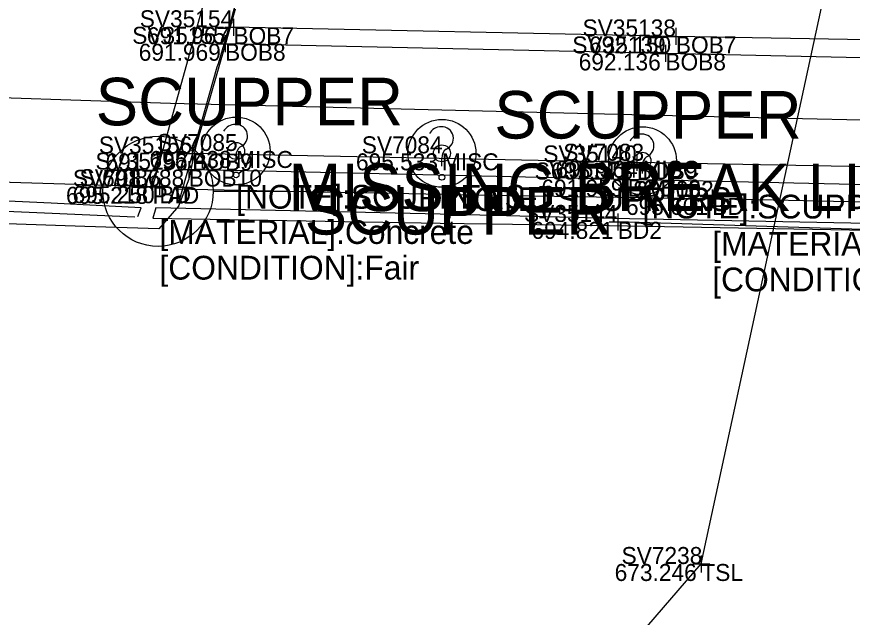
# Model space of a CAD drawing. Extents: x 1659932 to 1663108, y 619867 to 620611.
# Drawn here: x 1661219.34 to 1661268.55, y 620192.48 to 620227.86 of the extents above; entities that cross this region are included whole.
import ezdxf

# ---------------------------------------------------------------- set-up
doc = ezdxf.new("R2010")
doc.units = 0
for name, color, linetype in [('BR_X_Rail_Object', 7, 'Continuous'), ('BR_X_SV_Abut', 7, 'Continuous'), ('BR_X_SV_Bottom_of_Beam', 7, 'Continuous'), ('BR_X_SV_Bottom_of_Beam_Text', 7, 'Continuous'), ('BR_X_SV_Deck_Top', 7, 'Continuous'), ('BR_X_SV_Deck_Top_Text', 7, 'Continuous'), ('PM_X_Edge_Line', 7, 'Continuous'), ('RD_X_Concrete_Pad', 7, 'Continuous'), ('RD_X_Misc_Items', 7, 'Continuous'), ('RD_X_Text', 7, 'Continuous'), ('SC_Scratch6', 7, 'Continuous'), ('SV_X_Break_Lines', 7, 'Continuous'), ('SV_X_Shot_Marker', 7, 'Continuous'), ('SV_X_Text', 7, 'Continuous'), ('SV_X_Text_Comment', 7, 'Continuous'), ('SV_X_Text_Elevation', 7, 'Continuous'), ('SV_X_Text_Name', 7, 'Continuous'), ('SV_X_Toe_of_Slope', 7, 'Continuous')]:
    doc.layers.add(name, color=color, linetype=linetype)

msp = doc.modelspace()

# ---------------------------------------------------------------- linework, layer by layer
at = {"layer": 'BR_X_Rail_Object'}
for points in [[(1661226.468, 620216.098), (1661226.657, 620216.591), (1661221.357, 620216.868), (1661215.013, 620217.167), (1661213.348, 620217.079), (1661213.314, 620216.606), (1661216.002, 620216.515), (1661221.432, 620216.282), (1661226.299, 620216.071)], [(1661300.196, 620215.004), (1661277.496, 620215.529), (1661254.423, 620215.977), (1661244.278, 620216.225), (1661227.533, 620216.591), (1661227.344, 620215.991), (1661244.282, 620215.701), (1661254.224, 620215.561), (1661277.086, 620215.156), (1661299.829, 620214.642)]]:
    msp.add_lwpolyline(points, dxfattribs=at)
at = {"layer": 'BR_X_SV_Abut'}
msp.add_lwpolyline([(1661228.902, 620216.979), (1661231.137, 620224.905), (1661231.223, 620225.092), (1661232.028, 620227.843), (1661232.073, 620228.025), (1661233.318, 620232.429), (1661233.369, 620232.535), (1661233.962, 620235.423), (1661234.24, 620235.614), (1661235.509, 620239.905), (1661235.523, 620240.11), (1661236.345, 620242.714), (1661236.356, 620242.915), (1661238.766, 620251.347)], dxfattribs=at)
at = {"layer": 'BR_X_SV_Bottom_of_Beam'}
for points in [[(1661516.938, 620221.488), (1661491.079, 620222.019), (1661465.187, 620222.58), (1661439.251, 620223.092), (1661413.441, 620223.61), (1661387.584, 620224.174), (1661361.703, 620224.657), (1661335.742, 620225.126), (1661309.876, 620225.693), (1661284.015, 620226.238), (1661258.155, 620226.696), (1661232.1, 620227.235)], [(1661516.255, 620220.542), (1661490.624, 620220.907), (1661464.53, 620221.454), (1661438.64, 620222.101), (1661412.707, 620222.613), (1661386.76, 620223.066), (1661360.949, 620223.557), (1661335.05, 620224.176), (1661309.206, 620224.717), (1661283.267, 620225.126), (1661257.537, 620225.694), (1661231.605, 620226.262)], [(1661514.756, 620214.059), (1661488.914, 620214.555), (1661463.017, 620215.148), (1661437.126, 620215.616), (1661411.256, 620216.167), (1661385.428, 620216.691), (1661359.541, 620217.184), (1661333.602, 620217.682), (1661307.754, 620218.183), (1661281.891, 620218.773), (1661255.858, 620219.275), (1661229.67, 620219.799)], [(1661514.073, 620213.08), (1661488.21, 620213.597), (1661462.263, 620214.044), (1661436.515, 620214.643), (1661410.516, 620215.165), (1661384.602, 620215.601), (1661358.815, 620216.084), (1661332.968, 620216.701), (1661307.113, 620217.251), (1661281.101, 620217.691), (1661255.319, 620218.266), (1661229.464, 620218.851)]]:
    msp.add_lwpolyline(points, dxfattribs=at)
at = {"layer": 'BR_X_SV_Deck_Top'}
msp.add_lwpolyline([(1661513.529, 620210.295), (1661487.664, 620211.099), (1661461.66, 620211.354), (1661435.632, 620211.885), (1661409.962, 620212.424), (1661383.838, 620212.928), (1661332.298, 620213.947), (1661306.248, 620214.439), (1661280.429, 620214.969), (1661254.732, 620215.771)], dxfattribs=at)
at = {"layer": 'PM_X_Edge_Line'}
msp.add_lwpolyline([(1661202.201, 620223.591), (1661213.111, 620223.268), (1661228.394, 620222.766), (1661259.553, 620221.998), (1661275.152, 620221.639), (1661292.516, 620221.273), (1661314.563, 620220.783), (1661337.968, 620220.356), (1661364.828, 620219.904), (1661379.245, 620219.635), (1661405.952, 620219.205), (1661427.476, 620218.875), (1661447.989, 620218.475), (1661471.403, 620218.024), (1661496.022, 620217.585), (1661519.238, 620217.199), (1661540.284, 620216.766), (1661543.975, 620216.723)], dxfattribs=at)
at = {"layer": 'RD_X_Concrete_Pad'}
msp.add_lwpolyline([(1661227.337, 620217.837), (1661200.851, 620218.632), (1661210.18, 620250.901), (1661236.479, 620250.773)], close=True, dxfattribs=at)
at = {"layer": 'RD_X_Misc_Items'}
for p, q in [((1661232.255, 620219.193), (1661232.255, 620219.668)), ((1661244.378, 620219.055), (1661244.378, 620219.53)), ((1661256.189, 620218.618), (1661256.189, 620219.093))]:
    msp.add_line(p, q, dxfattribs=at)
for centre, radius in [((1661232.255, 620219.948), 2), ((1661244.378, 620219.81), 2), ((1661256.189, 620219.373), 2), ((1661232.255, 620219.948), 0.5), ((1661232.255, 620219.948), 0.5), ((1661244.378, 620219.81), 0.5), ((1661244.378, 620219.81), 0.5), ((1661256.189, 620219.373), 0.5), ((1661256.189, 620219.373), 0.5), ((1661232.255, 620218.536), 0.17), ((1661244.378, 620218.398), 0.17), ((1661256.189, 620217.961), 0.17)]:
    msp.add_circle(centre, radius, dxfattribs=at)
for centre, radius, start, end in [((1661232.191, 620220.759), 0.754, 88.324, 152.5385), ((1661232.243, 620220.826), 0.688, 291.9329, 92.4584), ((1661244.314, 620220.621), 0.754, 88.324, 152.5385), ((1661244.366, 620220.688), 0.688, 291.9329, 92.4584), ((1661256.125, 620220.184), 0.754, 88.324, 152.5385), ((1661256.177, 620220.251), 0.688, 291.9329, 92.4584), ((1661232.841, 620219.71), 0.587, 125.4618, 184.0829), ((1661244.964, 620219.572), 0.587, 125.4618, 184.0829), ((1661256.775, 620219.135), 0.587, 125.4618, 184.0829)]:
    msp.add_arc(centre, radius, start, end, dxfattribs=at)
at = {"layer": 'SC_Scratch6'}
msp.add_line((1661230.904, 620217.573), (1661235.334, 620217.573), dxfattribs=at)
msp.add_circle((1661227.66, 620217.573), 3.245, dxfattribs=at)
at = {"layer": 'SV_X_Break_Lines'}
for points in [[(1661228.886, 620216.719), (1661229.498, 620218.302), (1661229.927, 620220.312), (1661230.763, 620223.207), (1661231.636, 620226.217), (1661232.38, 620228.883), (1661234.027, 620234.579), (1661234.843, 620237.386), (1661236.169, 620242.084), (1661236.935, 620244.302), (1661237.536, 620246.886), (1661238.567, 620250.261), (1661238.784, 620251.123), (1661238.852, 620252.06)], [(1661228.67, 620217.714), (1661237.329, 620217.546), (1661248.531, 620217.329), (1661262.126, 620217.116), (1661283.4, 620216.641), (1661303.8, 620216.137), (1661335.243, 620215.455), (1661384.24, 620214.497), (1661403.674, 620214.086), (1661434.655, 620213.563), (1661466.755, 620212.973), (1661495.661, 620212.446), (1661513.396, 620212.012)], [(1661228.886, 620216.719), (1661227.706, 620215.362), (1661223.34, 620215.509), (1661219.318, 620215.645), (1661215.58, 620215.771), (1661211.999, 620215.892), (1661212.03, 620217.402)]]:
    msp.add_lwpolyline(points, dxfattribs=at)
at = {"layer": 'SV_X_Shot_Marker'}
for p, q in [((1661232.1, 620227.735), (1661232.1, 620226.735)), ((1661231.6, 620227.235), (1661232.6, 620227.235)), ((1661232.1, 620227.235), (1661232.1, 620227.235)), ((1661258.155, 620227.196), (1661258.155, 620226.196)), ((1661231.605, 620226.762), (1661231.605, 620225.762)), ((1661257.655, 620226.696), (1661258.655, 620226.696)), ((1661258.155, 620226.696), (1661258.155, 620226.696)), ((1661231.105, 620226.262), (1661232.105, 620226.262)), ((1661231.605, 620226.262), (1661231.605, 620226.262)), ((1661257.537, 620226.194), (1661257.537, 620225.194)), ((1661257.037, 620225.694), (1661258.037, 620225.694)), ((1661257.537, 620225.694), (1661257.537, 620225.694)), ((1661229.67, 620220.299), (1661229.67, 620219.299)), ((1661229.17, 620219.799), (1661230.17, 620219.799)), ((1661229.67, 620219.799), (1661229.67, 620219.799)), ((1661255.858, 620219.775), (1661255.858, 620218.775)), ((1661229.464, 620219.351), (1661229.464, 620218.351)), ((1661255.358, 620219.275), (1661256.358, 620219.275)), ((1661255.858, 620219.275), (1661255.858, 620219.275)), ((1661228.964, 620218.851), (1661229.964, 620218.851)), ((1661229.464, 620218.851), (1661229.464, 620218.851)), ((1661255.319, 620218.766), (1661255.319, 620217.766)), ((1661227.337, 620218.337), (1661227.337, 620217.337)), ((1661227.742, 620218.374), (1661227.742, 620217.374)), ((1661254.819, 620218.266), (1661255.819, 620218.266)), ((1661255.319, 620218.266), (1661255.319, 620218.266)), ((1661226.837, 620217.837), (1661227.837, 620217.837)), ((1661227.242, 620217.874), (1661228.242, 620217.874)), ((1661227.337, 620217.837), (1661227.337, 620217.837)), ((1661227.742, 620217.874), (1661227.742, 620217.874)), ((1661260.298, 620217.681), (1661260.298, 620216.681)), ((1661259.798, 620217.181), (1661260.798, 620217.181)), ((1661260.298, 620217.181), (1661260.298, 620217.181)), ((1661254.732, 620216.271), (1661254.732, 620215.271)), ((1661254.232, 620215.771), (1661255.232, 620215.771)), ((1661254.732, 620215.771), (1661254.732, 620215.771)), ((1661259.655, 620196.123), (1661259.655, 620195.123)), ((1661259.155, 620195.623), (1661260.155, 620195.623)), ((1661259.655, 620195.623), (1661259.655, 620195.623))]:
    msp.add_line(p, q, dxfattribs=at)
at = {"layer": 'SV_X_Toe_of_Slope'}
msp.add_lwpolyline([(1661237.229, 620169.637), (1661259.655, 620195.623), (1661277.405, 620277.795), (1661264.309, 620300.267)], dxfattribs=at)

# ---------------------------------------------------------------- texts
at = {"layer": 'BR_X_SV_Bottom_of_Beam_Text'}
for s, p in [('SV35154', (1661226.582, 620227.235)), ('SV35138', (1661252.658, 620226.696)), ('SV35155', (1661226.138, 620226.262)), ('691.967', (1661227.004, 620226.235)), ('BOB7', (1661232.1, 620226.235)), ('SV35139', (1661252.057, 620225.694)), ('692.150', (1661253.041, 620225.696)), ('BOB7', (1661258.155, 620225.696)), ('691.969', (1661226.521, 620225.262)), ('BOB8', (1661231.605, 620225.262)), ('692.136', (1661252.433, 620224.694)), ('BOB8', (1661257.537, 620224.694)), ('SV35156', (1661224.17, 620219.799)), ('SV35140', (1661250.348, 620219.275)), ('SV35157', (1661223.972, 620218.851)), ('691.796', (1661224.566, 620218.799)), ('BOB9', (1661229.67, 620218.799)), ('SV35141', (1661249.841, 620218.266)), ('691.973', (1661250.794, 620218.275)), ('BOB9', (1661255.858, 620218.275)), ('691.788', (1661224.364, 620217.851)), ('BOB10', (1661229.464, 620217.851)), ('691.959', (1661250.235, 620217.266)), ('BOB10', (1661255.319, 620217.266))]:
    msp.add_text(s, height=1, dxfattribs=at).set_placement(p)
at = {"layer": 'BR_X_SV_Deck_Top_Text'}
for s, p in [('SV7086', (1661223.04, 620217.874)), ('SV7082', (1661255.627, 620217.181)), ('695.250', (1661222.628, 620216.874)), ('BD', (1661227.742, 620216.874)), ('695.601', (1661255.216, 620216.181)), ('BD', (1661260.298, 620216.181)), ('SV35144', (1661249.214, 620215.771)), ('694.821', (1661249.65, 620214.771)), ('BD2', (1661254.732, 620214.771))]:
    msp.add_text(s, height=1, dxfattribs=at).set_placement(p)
at = {"layer": 'RD_X_Text'}
for p in [(1661223.988, 620221.459), (1661247.461, 620220.68), (1661236.292, 620215.027)]:
    msp.add_text('SCUPPER', height=2.8, dxfattribs=at).set_placement(p)
at = {"layer": 'SC_Scratch6'}
msp.add_text('MISSING BREAK LINES', height=2.79999, dxfattribs=at).set_placement((1661235.334, 620216.406))
at = {"layer": 'SV_X_Text'}
for s, p in [('[NOTE]:SCUPPERS', (1661232.255, 620216.548)), ('[NOTE]:SCUPPERS', (1661244.378, 620216.41)), ('[NOTE]:SCUPPERS', (1661256.189, 620215.973)), ('[MATERIAL]:Concrete', (1661227.742, 620214.474)), ('[MATERIAL]:Concrete', (1661260.298, 620213.781)), ('[CONDITION]:Fair', (1661227.742, 620212.374)), ('[CONDITION]:Fair', (1661260.298, 620211.681))]:
    msp.add_text(s, height=1.4, dxfattribs=at).set_placement(p)
at = {"layer": 'SV_X_Text_Comment'}
for s, p in [('MISC', (1661232.255, 620218.948)), ('MISC', (1661244.378, 620218.81)), ('MISC', (1661256.189, 620218.373)), ('PAD', (1661227.337, 620216.837)), ('TSL', (1661259.655, 620194.623))]:
    msp.add_text(s, height=1, dxfattribs=at).set_placement(p)
at = {"layer": 'SV_X_Text_Elevation'}
for s, p in [('695.438', (1661227.155, 620218.948)), ('695.533', (1661239.314, 620218.81)), ('695.564', (1661251.067, 620218.373)), ('695.218', (1661222.237, 620216.837)), ('673.246', (1661254.551, 620194.623))]:
    msp.add_text(s, height=1, dxfattribs=at).set_placement(p)
at = {"layer": 'SV_X_Text_Name'}
for s, p in [('SV7085', (1661227.586, 620219.948)), ('SV7084', (1661239.658, 620219.81)), ('SV7083', (1661251.527, 620219.373)), ('SV7087', (1661222.643, 620217.837)), ('SV7238', (1661254.956, 620195.623))]:
    msp.add_text(s, height=1, dxfattribs=at).set_placement(p)

doc.saveas('drawing.dxf')
